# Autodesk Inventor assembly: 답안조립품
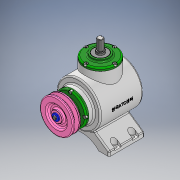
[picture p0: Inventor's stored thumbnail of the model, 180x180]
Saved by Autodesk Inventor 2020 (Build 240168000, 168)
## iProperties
Created: 2023-12
Part Number: 답안조립품
Document SubType Name: Weldment
Designer: 1강의실14
Weld Material: Welded Aluminum-6061
Author: 1강의실14
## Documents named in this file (17)
- C:\Users\1강의실14\Desktop\731203V1004\답안조립품.iam
- C:\Users\1강의실14\Desktop\731203V1004\본체.ipt
- C:\Users\1강의실14\Desktop\731203V1004\커버.ipt
- C:\Users\1강의실14\Desktop\731203V1004\베어링 6203.ipt
- C:\Users\1강의실14\Desktop\731203V1004\오일실 17 x 32 x 8.ipt
- C:\Users\1강의실14\Desktop\731203V1004\메인 축.ipt
- 메인 축.ipt
- C:\Users\1강의실14\Desktop\731203V1004\키 5 x 5 x 14.ipt
- C:\Users\1강의실14\Desktop\731203V1004\메인 베벨기어.ipt
- C:\Users\1강의실14\Desktop\731203V1004\서브 축.ipt
- 서브 축.ipt
- C:\Users\1강의실14\Desktop\731203V1004\키 4 x 4 x 14.ipt
- C:\Users\1강의실14\Desktop\731203V1004\서브 베벨기어.ipt
- C:\Users\1강의실14\Desktop\731203V1004\V-벨트풀리.ipt
- C:\Users\1강의실14\Desktop\731203V1004\와셔 4 x 16.ipt
- C:\Users\1강의실14\Desktop\731203V1004\육각볼트 M4 x 8.ipt
- C:\Users\1강의실14\Desktop\731203V1004\볼트 M4 x 10.ipt
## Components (1 placed, 1 different names)
1. V-벨트풀리:1
